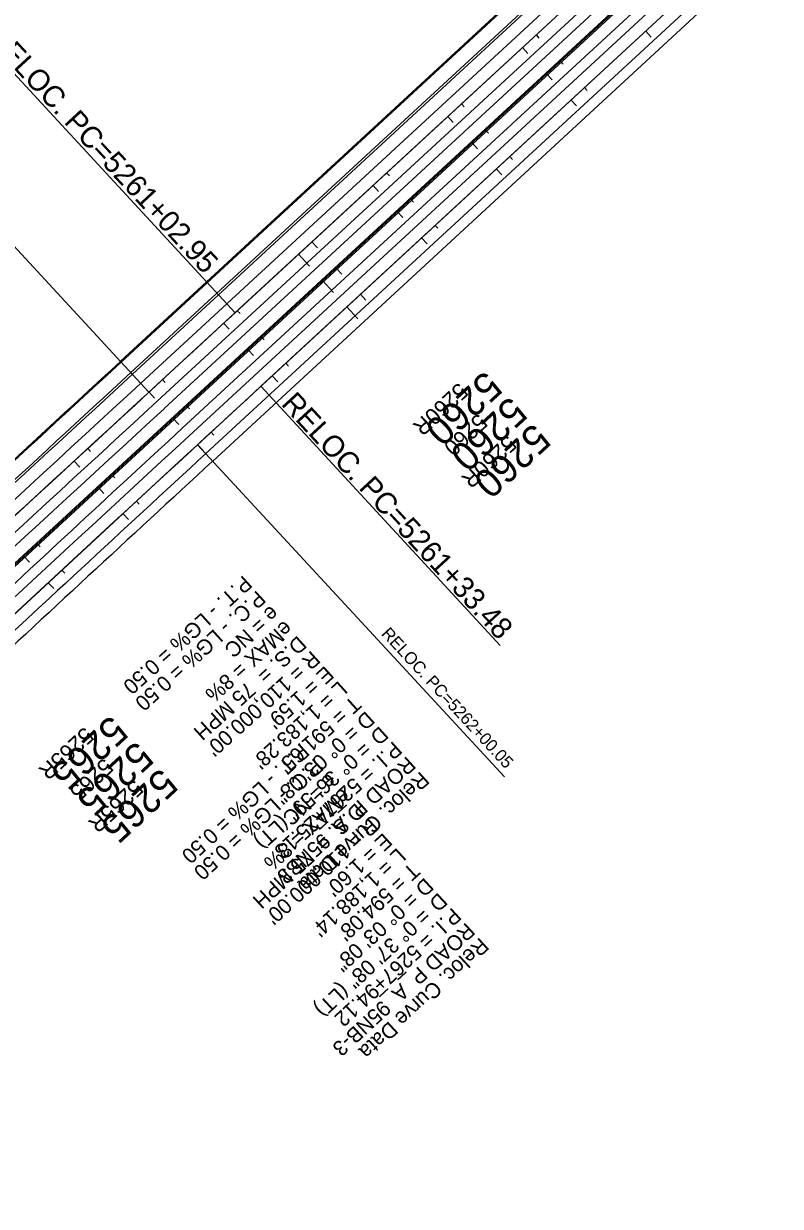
# Model space of a CAD drawing. Extents: x 2160876 to 2175990, y 601436 to 618246.
# Drawn here: x 2165449 to 2166193, y 606830 to 607994 of the extents above; entities that cross this region are included whole.
import ezdxf

# ---------------------------------------------------------------- set-up
doc = ezdxf.new("R2010")
doc.units = 0
for name, color, linetype in [('BNDY-ADJ', 7, 'Continuous'), ('BNDY-ADJ-TXT', 7, 'Continuous'), ('EX-UTIL-ELEC-TXT', 7, 'Continuous'), ('GN_Transparent 80', 7, 'Continuous'), ('RD_DTM_Major2', 7, 'Continuous'), ('RD_EX_BldgApp_Steps', 7, 'Continuous'), ('RD_EX_DV_TX_Prop', 7, 'Continuous'), ('RD_HC_Cl', 7, 'Continuous'), ('RD_HC_Data_Tic', 7, 'Continuous'), ('RD_HC_TX_Sta50', 7, 'Continuous'), ('RD_TX_RoadID', 7, 'Continuous')]:
    doc.layers.add(name, color=color, linetype=linetype)

msp = doc.modelspace()

# ---------------------------------------------------------------- linework, layer by layer
at = {"layer": 'BNDY-ADJ'}
msp.add_line((2172239.9, 613739.9), (2163704.8, 605858.6), dxfattribs=at)
at = {"layer": 'BNDY-ADJ-TXT'}
for p, q in [((2168658.1, 610480.3), (2165572.4, 607631)), ((2168705.8, 610428.6), (2165620.1, 607579.3))]:
    msp.add_line(p, q, dxfattribs=at)
for centre, start, end in [((2090947.4, 688446.2), 312.100607, 312.719474), ((2240245.2, 526764.1), 132.719474, 133.338341)]:
    msp.add_arc(centre, 110000, start, end, dxfattribs=at)
at = {"layer": 'EX-UTIL-ELEC-TXT'}
for p, q in [((2168630.1, 610510.7), (2165544.4, 607661.4)), ((2168630.7, 610509.9), (2165545.1, 607660.6)), ((2168650, 610489.1), (2165564.3, 607639.8)), ((2168658.1, 610480.3), (2165572.4, 607631)), ((2168666.2, 610471.5), (2165580.6, 607622.2)), ((2168697.7, 610437.5), (2165612, 607588.1)), ((2168705.8, 610428.6), (2165620.1, 607579.3)), ((2168714, 610419.8), (2165628.3, 607570.5))]:
    msp.add_line(p, q, dxfattribs=at)
for centre, radius, start, end in [((2090947.4, 688446.2), 109958.7, 312.303996, 312.719474), ((2090947.4, 688446.2), 109959.7, 312.303996, 312.719474), ((2090947.4, 688446.2), 109988, 312.100607, 312.719474), ((2090947.4, 688446.2), 110000, 312.100607, 312.719474), ((2090947.4, 688446.2), 110012, 312.100607, 312.719474), ((2240245.2, 526764.1), 110012, 132.719474, 133.338341), ((2240245.2, 526764.1), 110000, 132.719474, 133.338341), ((2240245.2, 526764.1), 109988, 132.719474, 133.067682)]:
    msp.add_arc(centre, radius, start, end, dxfattribs=at)
at = {"layer": 'GN_Transparent 80'}
for p, q in [((2168640.2, 610499.7), (2165554.6, 607650.3)), ((2168641.8, 610497.9), (2165556.1, 607648.6)), ((2168454, 610245.6), (2165100.2, 607148.7)), ((2168455.6, 610243.9), (2165101.8, 607146.9))]:
    msp.add_line(p, q, dxfattribs=at)
for radius, start in [(109973.7, 312.303996), (109976, 312.30394)]:
    msp.add_arc((2090947.4, 688446.2), radius, start, 312.719474, dxfattribs=at)
at = {"layer": 'RD_DTM_Major2'}
for p, q in [((2165963.6, 607944.4), (2165969.1, 607938.5)), ((2165890.2, 607876.5), (2165895.6, 607870.6)), ((2165816.7, 607808.7), (2165822.1, 607802.8)), ((2165743.2, 607740.8), (2165754.1, 607729.1)), ((2165669.8, 607673), (2165675.2, 607667.1)), ((2165596.3, 607605.2), (2165601.7, 607599.3)), ((2165522.8, 607537.3), (2165528.2, 607531.4)), ((2165449.3, 607469.5), (2165454.8, 607463.6))]:
    msp.add_line(p, q, dxfattribs=at)
at = {"layer": 'RD_EX_BldgApp_Steps'}
for p, q in [((2172672.7, 614139.6), (2163700.6, 605854.7)), ((2169773.5, 611510.3), (2165657.1, 607709.2)), ((2169821.3, 611458.6), (2165682.4, 607636.8)), ((2165953.2, 607982.6), (2165955.9, 607979.6)), ((2165657.1, 607709.2), (2165410.9, 607975.9)), ((2165977, 607956.7), (2165979.8, 607953.8)), ((2166000.9, 607930.9), (2166003.6, 607928)), ((2165879.7, 607914.7), (2165882.4, 607911.8)), ((2165903.6, 607888.9), (2165906.3, 607886)), ((2165927.4, 607863.1), (2165930.1, 607860.1)), ((2165806.2, 607846.9), (2165809, 607844)), ((2165830.1, 607821.1), (2165832.8, 607818.1)), ((2165854, 607795.2), (2165856.7, 607792.3)), ((2165732.8, 607779.1), (2165738.2, 607773.2)), ((2165756.6, 607753.2), (2165762.1, 607747.3)), ((2165780.5, 607727.4), (2165785.9, 607721.5)), ((2165659.3, 607711.2), (2165662, 607708.3)), ((2165683.2, 607685.4), (2165685.9, 607682.4)), ((2165707, 607659.5), (2165709.7, 607656.6)), ((2165585.8, 607643.4), (2165588.5, 607640.5)), ((2165682.4, 607636.8), (2165917.9, 607381.8)), ((2165609.7, 607617.5), (2165612.4, 607614.6)), ((2165633.6, 607591.7), (2165636.3, 607588.8)), ((2165512.3, 607575.7), (2165515, 607572.7)), ((2165536.2, 607549.7), (2165538.9, 607546.8)), ((2165560.2, 607523.8), (2165562.9, 607520.8)), ((2165462.8, 607481.9), (2165465.5, 607478.9)), ((2165486.8, 607455.8), (2165489.6, 607452.9))]:
    msp.add_line(p, q, dxfattribs=at)
for centre, start, end in [((2091032.1, 688524.5), 312.095186, 312.719474), ((2240307.5, 526821.6), 132.719474, 133.335811)]:
    msp.add_arc(centre, 110000, start, end, dxfattribs=at)
at = {"layer": 'RD_HC_Cl'}
for p, q in [((2166061, 607986.4), (2166066.4, 607980.5)), ((2165939.8, 607970.2), (2165945.2, 607964.4)), ((2165987.5, 607918.6), (2165992.9, 607912.7)), ((2165866.3, 607902.4), (2165871.8, 607896.5)), ((2165914.1, 607850.7), (2165919.5, 607844.8)), ((2165792.9, 607834.5), (2165798.3, 607828.7)), ((2165840.6, 607782.9), (2165846, 607777)), ((2165719.4, 607766.7), (2165730.3, 607755)), ((2165767.1, 607715), (2165778, 607703.3)), ((2165645.9, 607698.9), (2165651.4, 607693)), ((2165693.6, 607647.2), (2165699.1, 607641.3)), ((2165572.5, 607631), (2165577.9, 607625.1)), ((2165620.2, 607579.4), (2165625.6, 607573.5)), ((2165499, 607563.2), (2165504.4, 607557.3)), ((2165546.7, 607511.5), (2165552.2, 607505.6)), ((2165473.4, 607443.5), (2165478.8, 607437.7))]:
    msp.add_line(p, q, dxfattribs=at)
at = {"layer": 'RD_HC_TX_Sta50'}
for p, q in [((2165572.4, 607631), (2165311.5, 607913.6)), ((2165620.1, 607579.3), (2165922.1, 607252.3))]:
    msp.add_line(p, q, dxfattribs=at)
at = {"layer": 'RD_TX_RoadID'}
for p, q in [((2168641.8, 610497.9), (2165556.1, 607648.6)), ((2168673, 610464.1), (2165587.4, 607614.8)), ((2168690.9, 610444.8), (2165605.2, 607595.5)), ((2168720.7, 610412.5), (2165635.1, 607563.2))]:
    msp.add_line(p, q, dxfattribs=at)
for centre, radius, start, end in [((2090947.4, 688446.2), 109976, 312.30394, 312.719474), ((2090947.4, 688446.2), 110022, 312.100607, 312.719474), ((2240245.2, 526764.1), 110022, 132.719474, 133.338341), ((2240245.2, 526764.1), 109978, 132.719474, 133.067545)]:
    msp.add_arc(centre, radius, start, end, dxfattribs=at)

# ---------------------------------------------------------------- texts
at = {"layer": 'RD_EX_BldgApp_Steps'}
for s, height, rotation, p in [('RELOC. PC=5261+02.95', 21, 312.7195, (2165411.9, 607979.1)), ('5260', 28, 222.7195, (2165903.2, 607653.3)), ('RELOC. PC=5261+33.48', 21, 312.7195, (2165701.7, 607618.9)), ('5260', 28, 222.7195, (2165927.8, 607628.1)), ('5260', 28, 222.7195, (2165950.9, 607601.7)), ('P.T. - LG% = 0.50', 15, 222.0714, (2165665.3, 607451.5)), ('P.C. - LG% = 0.50', 15, 222.0714, (2165678.7, 607436.7)), ('e = NC', 15, 222.0714, (2165692.1, 607421.8)), ('eMAX = 8%', 15, 222.0714, (2165705.5, 607407)), ('D.S. =  75 MPH', 15, 222.0714, (2165718.9, 607392.1)), ("R = 110,000.00'", 15, 222.0714, (2165732.3, 607377.3)), ("E = 1.59'", 15, 222.0714, (2165745.7, 607362.4)), ("L = 1,183.28'", 15, 222.0714, (2165759.1, 607347.6)), ("T = 591.65'", 15, 222.0714, (2165772.5, 607332.8)), ('D = 0° 03\' 08"', 15, 222.0714, (2165785.9, 607317.9)), ('5265', 28, 222.5127, (2165535.2, 607314.3)), ('D', 15, 222.0714, (2165799.4, 607303.1)), ('5265', 28, 222.7195, (2165560.3, 607288.8)), ('    = 0° 36\' 59" (LT)', 15, 222.0714, (2165799.4, 607303.1)), ('P.I. = 5267+25.13', 15, 222.0714, (2165812.8, 607288.2)), ('ROAD P_A_95NB3', 15, 222.0714, (2165826.2, 607273.4)), ('5265', 28, 222.9104, (2165584.1, 607262.3)), ('Reloc. Curve Data', 15, 222.0714, (2165839.6, 607258.5))]:
    msp.add_text(s, height=height, rotation=rotation, dxfattribs=at).set_placement(p)
at = {"layer": 'RD_EX_DV_TX_Prop'}
for s, p in [('5260', (2165896.1, 607610.9)), ('5265', (2165528.1, 607271.7))]:
    msp.add_text(s, height=16, rotation=222.7195, dxfattribs=at).set_placement(p)
at = {"layer": 'RD_HC_Data_Tic'}
for s, rotation, p in [('5260R', 222.7195, (2165877.1, 607641.3)), ('5260R', 222.7195, (2165924.8, 607589.6)), ('5265R', 222.5632, (2165509, 607302.4)), ('5265R', 222.8757, (2165557.6, 607250.6))]:
    msp.add_text(s, height=16, rotation=rotation, dxfattribs=at).set_placement(p)
at = {"layer": 'RD_HC_TX_Sta50'}
for s, height, rotation, p in [('RELOC. PC=5262+00.05', 12, 312.7195, (2165800.3, 607392.7)), ('P.T. - LG% = 0.50', 15, 222.7195, (2165721.6, 607286.1)), ('P.C. - LG% = 0.50', 15, 222.7195, (2165735.2, 607271.4)), ('e = NC', 15, 222.7195, (2165748.7, 607256.8)), ('eMAX = 8%', 15, 222.7195, (2165762.3, 607242.1)), ('D.S. =  75 MPH', 15, 222.7195, (2165775.9, 607227.4)), ("R = 110,000.00'", 15, 222.7195, (2165789.4, 607212.7)), ("E = 1.60'", 15, 222.7195, (2165803, 607198)), ("L = 1,188.14'", 15, 222.7195, (2165816.6, 607183.3)), ("T = 594.08'", 15, 222.7195, (2165830.1, 607168.6)), ('D = 0° 03\' 08"', 15, 222.7195, (2165843.7, 607153.9)), ('D', 15, 222.7195, (2165857.3, 607139.2)), ('    = 0° 37\' 08" (LT)', 15, 222.7195, (2165857.3, 607139.2)), ('P.I. = 5267+94.12', 15, 222.7195, (2165870.9, 607124.5)), ('ROAD P_A_95NB-3', 15, 222.7195, (2165884.4, 607109.8)), ('Reloc. Curve Data', 15, 222.7195, (2165898, 607095.1))]:
    msp.add_text(s, height=height, rotation=rotation, dxfattribs=at).set_placement(p)

doc.saveas('drawing.dxf')
